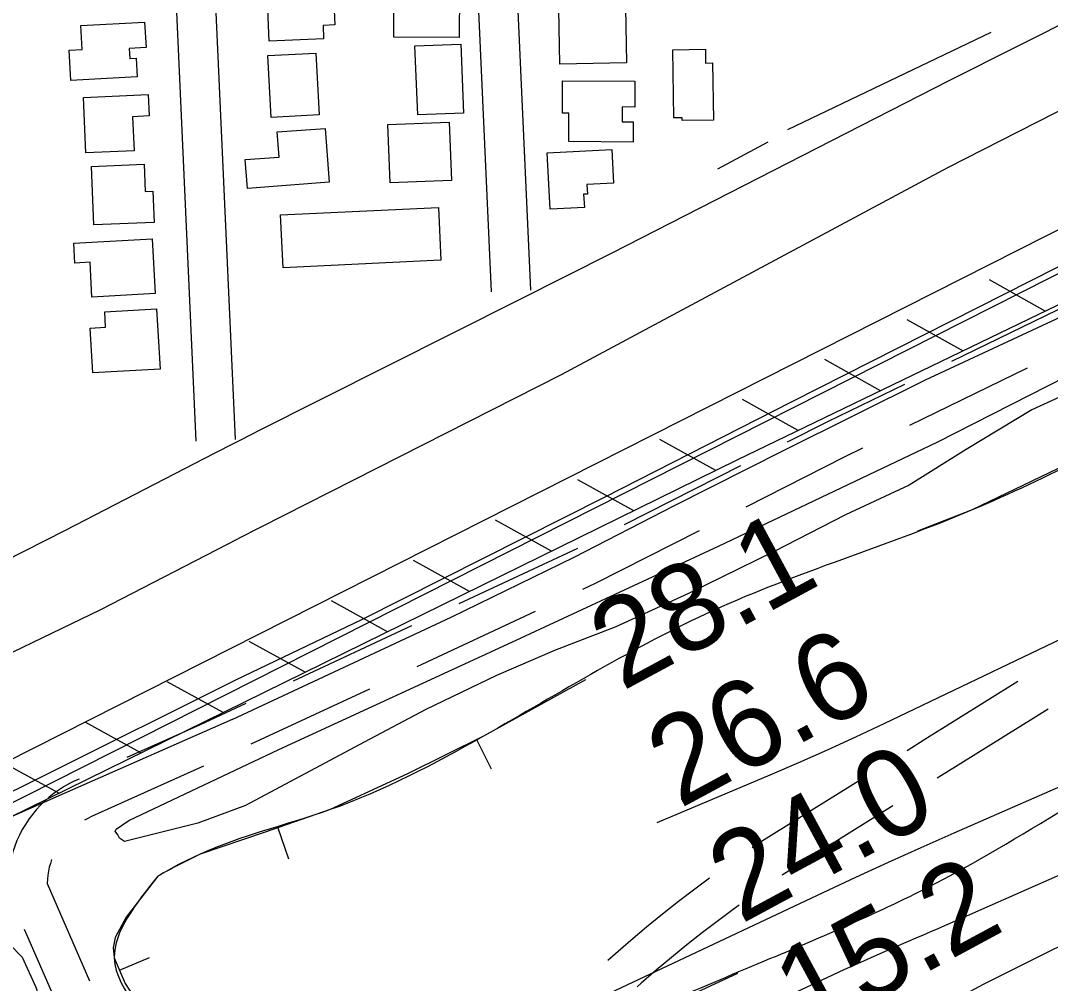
# Model space of a CAD drawing. Extents: x 3598634 to 3636690, y 517270 to 542944.
# Drawn here: x 3610665 to 3611452, y 535580 to 536317 of the extents above; entities that cross this region are included whole.
import ezdxf

# ---------------------------------------------------------------- set-up
doc = ezdxf.new("R2010")
doc.units = 0
for name, color, linetype in [('V-BLDG-OTLN', 7, 'Continuous'), ('V-BORW-LINE', 7, 'Continuous'), ('V-FLOD-BASE', 7, 'Continuous'), ('V-LEVE-TOET', 7, 'Continuous'), ('V-RIVR-RANG', 7, 'Continuous'), ('V-ROAD-CNTR', 7, 'Continuous'), ('V-RRAP-FSHR', 7, 'Continuous'), ('V-SITE-VEGE', 7, 'Continuous'), ('V-SURV-LINE', 7, 'Continuous'), ('V-TOPO-DPTH', 7, 'Continuous'), ('V-TOPO-MAJR', 7, 'Continuous'), ('V-TOPO-MINR', 7, 'Continuous'), ('V-TOPO-SHOR', 7, 'Continuous')]:
    doc.layers.add(name, color=color, linetype=linetype)

msp = doc.modelspace()

# ---------------------------------------------------------------- linework, layer by layer
at = {"layer": 'V-BLDG-OTLN'}
for points in [[(3610852.94, 536344.03), (3610893.77, 536345.78), (3610894.19, 536336.04), (3610904.04, 536336.46), (3610905.02, 536313.64), (3610895.97, 536313.26), (3610896.41, 536302.93), (3610854.78, 536301.15)], [(3611000.22, 536304.1), (3610950.08, 536304.35), (3610950.21, 536329.05), (3610961.4, 536329), (3610961.51, 536350.75), (3610986.63, 536350.62), (3610986.57, 536339.04), (3611000.4, 536338.97)], [(3611128.09, 536284.69), (3611077.2, 536283.66), (3611076.34, 536325.66), (3611127.24, 536326.69)], [(3610710.66, 536313.19), (3610759.46, 536315.83), (3610760.52, 536296.26), (3610747.64, 536295.56), (3610748.05, 536287.98), (3610753.05, 536288.25), (3610753.83, 536273.92), (3610702.89, 536271.15), (3610701.63, 536294.28), (3610711.66, 536294.82)], [(3610968.38, 536244.8), (3610966.31, 536297.49), (3611001.26, 536298.87), (3611003.33, 536246.17)], [(3610893, 536244.84), (3610856.28, 536242.85), (3610853.73, 536290.12), (3610890.45, 536292.1)], [(3611164.33, 536242.43), (3611163.56, 536294.59), (3611188.47, 536294.96), (3611188.63, 536284.42), (3611193.93, 536284.5), (3611194.58, 536240.84), (3611170.81, 536240.48), (3611170.79, 536242.52)], [(3611083.92, 536224.31), (3611084.07, 536246.16), (3611079.11, 536246.19), (3611079.28, 536270.89), (3611134.63, 536270.52), (3611134.5, 536250.76), (3611124.93, 536250.82), (3611124.85, 536239.45), (3611133.22, 536239.39), (3611133.12, 536223.98)], [(3610714.57, 536215.6), (3610712.6, 536258.12), (3610762.1, 536260.41), (3610762.86, 536243.94), (3610750.12, 536243.35), (3610751.33, 536217.3)], [(3610945.53, 536237.48), (3610992.58, 536239.27), (3610994.27, 536194.55), (3610947.23, 536192.77)], [(3610860.98, 536231.66), (3610897.48, 536234.41), (3610900.58, 536193.26), (3610838.09, 536188.54), (3610836.43, 536210.49), (3610862.43, 536212.45)], [(3611067.51, 536215.74), (3611116.86, 536218.3), (3611118.2, 536192.49), (3611097.85, 536191.44), (3611098.23, 536184.12), (3611095.34, 536183.97), (3611095.87, 536173.84), (3611069.76, 536172.48)], [(3610766.69, 536162.47), (3610720.68, 536160.52), (3610718.78, 536205.2), (3610759.09, 536206.91), (3610759.97, 536186.24), (3610765.67, 536186.48)], [(3610863.5, 536168.16), (3610984.26, 536173.91), (3610986.19, 536133.44), (3610865.43, 536127.68)], [(3610705.31, 536146.62), (3610765.26, 536149.94), (3610767.57, 536108.05), (3610719.14, 536105.37), (3610717.67, 536131.98), (3610706.15, 536131.34)], [(3610768.59, 536096.26), (3610771.25, 536050.25), (3610719.73, 536047.27), (3610717.74, 536081.6), (3610729.62, 536082.29), (3610728.94, 536093.96)]]:
    msp.add_lwpolyline(points, close=True, dxfattribs=at)
at = {"layer": 'V-BORW-LINE'}
for p, q in [((3611013.49, 535766.62), (3611024.62, 535744.24)), ((3610861.42, 535699.1), (3610869.62, 535675.48)), ((3610740.25, 535590.16), (3610763.25, 535599.96))]:
    msp.add_line(p, q, dxfattribs=at)
for points in [[(3612023.85, 536263.17), (3611980.78, 536247.05), (3611892.58, 536209.71), (3611807.94, 536161.5), (3611723.45, 536113.04), (3611642.68, 536069.34), (3611561.62, 536026.13), (3611477.6, 535983.35), (3611392.7, 535942.4), (3611350.75, 535926.22)], [(3611096.73, 535812.4), (3611018.78, 535769.25), (3610960.51, 535740.3), (3610901.46, 535713), (3610851.78, 535695.75), (3610801.89, 535678.85), (3610785.43, 535671.05), (3610769.5, 535662.11)], [(3610769.5, 535662.11), (3610745.31, 535630.77), (3610736.96, 535615.08), (3610735.41, 535607.29), (3610736.24, 535599.58), (3610744.62, 535579.91), (3610782.45, 535521.14), (3610796.61, 535489.26), (3610804.12, 535473.17), (3610813.88, 535457.77), (3610825.62, 535446.59), (3610838.02, 535440.11), (3610863.05, 535435.2), (3610883.35, 535435.96), (3610913.73, 535442.49), (3610940.89, 535453.25), (3611010.93, 535490.43), (3611081.63, 535526.87), (3611157.62, 535562.1), (3611213.26, 535587.79)]]:
    msp.add_lwpolyline(points, dxfattribs=at)
msp.add_spline([(3610769.5, 535662.11), (3610801.89, 535678.85), (3610901.46, 535713), (3611018.78, 535769.25), (3611194.65, 535865.45), (3611392.7, 535942.4), (3611561.62, 536026.13), (3611723.45, 536113.04), (3611892.58, 536209.71), (3612070.48, 536280.62), (3612177.1, 536337.19), (3612328.43, 536346.09), (3612365.39, 536274.98), (3612320.44, 536188.1), (3612159.82, 536071.64), (3611939.35, 535952.99), (3611770.69, 535869.03), (3611577.59, 535780.59), (3611364.8, 535656.78), (3611233.69, 535597.22), (3611081.63, 535526.87), (3610940.89, 535453.25), (3610813.88, 535457.77), (3610782.45, 535521.14), (3610736.24, 535599.58), (3610769.5, 535662.11)], degree=3, dxfattribs=at)
at = {"layer": 'V-FLOD-BASE'}
for points in [[(3613126.88, 536947.9), (3613005.88, 536895.75), (3612842.67, 536822.62), (3612628.59, 536720.77), (3612427.84, 536620.78), (3612265.19, 536538.42), (3612118.66, 536463.83), (3611925.34, 536363.88), (3611722.56, 536259.52), (3611477.81, 536138.03), (3611254.56, 536025.11), (3611111.09, 535951.82), (3610925.94, 535858.58), (3610829.1, 535812.18)], [(3610829.1, 535812.18), (3610682.85, 535739.24), (3610548.17, 535672.38), (3610508.72, 535652.79), (3610480.82, 535635.89), (3610442.72, 535611.55), (3610412.09, 535588.54), (3610378.04, 535560.11), (3610264.32, 535459.22)]]:
    msp.add_lwpolyline(points, dxfattribs=at)
at = {"layer": 'V-LEVE-TOET'}
for points in [[(3613678.75, 537323.7), (3613393.93, 537188.74), (3613238.46, 537113.49), (3613220.45, 537105.54), (3613196.7, 537095.05), (3613084.29, 537034.65), (3612874.5, 536938.84), (3612572.47, 536804.82), (3612341.69, 536695.81), (3612081.23, 536565.59), (3611875.04, 536468.26), (3611591.08, 536315.07), (3611373.66, 536204.33), (3611078.17, 536045.69), (3610830.76, 535920.18)], [(3610826.51, 535782.03), (3610993.88, 535860.21), (3611087.99, 535906.32), (3611164.46, 535945.43), (3611248.85, 535988.16), (3611356.77, 536042.04), (3611457.04, 536088.7), (3611536.58, 536127.31), (3611632.74, 536173.43), (3611724.28, 536222.36), (3611836.02, 536282.41), (3611934.24, 536329.06), (3612029.61, 536379.54), (3612118.59, 536427.43), (3612198.89, 536468.09), (3612286.11, 536509.3), (3612375.87, 536555.39), (3612453.87, 536594.25), (3612521.87, 536632.79), (3612612.67, 536675.56)], [(3610613.78, 535812.11), (3610726, 535866.13), (3610830.76, 535920.18)], [(3610826.51, 535782.03), (3610633.37, 535696.99)]]:
    msp.add_lwpolyline(points, dxfattribs=at)
at = {"layer": 'V-ROAD-CNTR'}
for p, q in [((3611466.65, 536099.75), (3611376.73, 536055.99)), ((3611434.68, 536050.83), (3611344.76, 536007.07)), ((3611215.42, 535976.13), (3611126.23, 535930.91)), ((3611090.55, 535912.84), (3610999.96, 535870.5)), ((3611058.24, 535864.62), (3610967.65, 535822.29)), ((3610963.72, 535853.57), (3610873.13, 535811.23)), ((3610931.41, 535805.35), (3610840.81, 535763.01)), ((3610667.38, 535621.59), (3610707.42, 535529.96))]:
    msp.add_line(p, q, dxfattribs=at)
for points in [[(3613504.37, 537298.19), (3613263.07, 537189.72), (3613226.18, 537173.13), (3612903.99, 537025.29), (3612651.67, 536909.6), (3612381.21, 536778.17), (3612102.85, 536636.7), (3612024.44, 536597.32), (3611881.03, 536525.28), (3611648.71, 536408.92), (3611528.47, 536348.32), (3611374.7, 536270.81), (3611116.81, 536138.94), (3611045.59, 536103.07), (3610844.51, 536001.96)], [(3610979.38, 537109.97), (3611024.59, 536109.29)], [(3611009.35, 537111.33), (3611054.56, 536110.65)], [(3610749.63, 537082.42), (3610798.67, 535995.03)], [(3610779.6, 537083.77), (3610828.64, 535996.38)], [(3611340.77, 536038.49), (3611281.9, 536009.84), (3611251.1, 535994.22)], [(3610605.3, 535879.54), (3610698.94, 535926.98), (3610813.03, 535985.75), (3610844.51, 536001.96)], [(3611308.79, 535989.56), (3611295.25, 535982.97), (3611219.49, 535944.56)], [(3611183.82, 535926.47), (3611104.24, 535886.12), (3611094.48, 535881.56)], [(3611427.62, 535811.05), (3611356.47, 535766.71), (3611342.76, 535758.15)], [(3610836.89, 535794.29), (3610802.06, 535778.02), (3610745.9, 535752.81)], [(3611450.63, 535790.04), (3611372.35, 535741.26), (3611365.77, 535737.15)], [(3610804.51, 535746.23), (3610718.8, 535707.77), (3610715.91, 535706.36), (3610713.43, 535704.98)], [(3610709.41, 535736.44), (3610706.07, 535734.94), (3610702.03, 535732.97), (3610697.96, 535730.7), (3610694.01, 535728.23), (3610690.2, 535725.54), (3610686.54, 535722.67), (3610683.04, 535719.6), (3610679.71, 535716.35), (3610676.55, 535712.93), (3610673.58, 535709.34), (3610670.8, 535705.61), (3610668.23, 535701.73), (3610665.86, 535697.72), (3610663.71, 535693.59), (3610661.78, 535689.35), (3610660.08, 535685.01), (3610658.61, 535680.6), (3610657.38, 535676.11), (3610656.39, 535671.56), (3610656.26, 535670.77)], [(3611308.84, 535736.95), (3611231.51, 535688.62), (3611224.23, 535683.67)], [(3611331.85, 535715.95), (3611247.9, 535663.49), (3611247.07, 535662.92)], [(3610688.32, 535674.86), (3610688.3, 535674.8), (3610687.33, 535671.89), (3610686.52, 535668.93), (3610685.87, 535665.94), (3610685.37, 535662.91), (3610685.04, 535659.87), (3610684.87, 535656.81), (3610684.87, 535656.5), (3610717.39, 535582.08)], [(3611191.58, 535660.57), (3611180.33, 535652.19), (3611167.91, 535642.65), (3611155.62, 535632.94), (3611143.48, 535623.05), (3611131.48, 535612.98), (3611119.62, 535602.74), (3611113.9, 535597.65)], [(3611214.29, 535640), (3611210.64, 535637.36), (3611198.43, 535628.26), (3611186.35, 535618.99), (3611174.4, 535609.54), (3611162.59, 535599.92), (3611150.92, 535590.14), (3611139.4, 535580.18), (3611136.32, 535577.45)]]:
    msp.add_lwpolyline(points, dxfattribs=at)
at = {"layer": 'V-RRAP-FSHR'}
for p, q in [((3611448.49, 536094.6), (3611405.87, 536118.43)), ((3611385.47, 536064.14), (3611342.84, 536087.97)), ((3611322.44, 536033.68), (3611279.82, 536057.51)), ((3611259.41, 536003.22), (3611216.79, 536027.05)), ((3611196.44, 535972.66), (3611153.66, 535996.2)), ((3611133.62, 535941.78), (3611090.84, 535965.33)), ((3611070.79, 535910.91), (3611028.01, 535934.45)), ((3611007.97, 535880.03), (3610965.19, 535903.58)), ((3610945.15, 535849.16), (3610902.37, 535872.71)), ((3610882.32, 535818.28), (3610839.55, 535841.83)), ((3610819.5, 535787.41), (3610776.72, 535810.96)), ((3610756.68, 535756.54), (3610713.9, 535780.08)), ((3610693.85, 535725.66), (3610651.08, 535749.21))]:
    msp.add_line(p, q, dxfattribs=at)
for points in [[(3610283.69, 535468.85), (3610304.82, 535469.21), (3610403.34, 535553.55), (3610452.08, 535596.07), (3610565.02, 535662.34), (3611212.78, 535980.69), (3611755.64, 536243.03), (3612146.76, 536451.69), (3612655.72, 536703.7), (3613040.11, 536882.25), (3613115.54, 536910.69), (3613121.06, 536940.01)], [(3610283.69, 535468.85), (3610304.82, 535469.21), (3610403.34, 535553.55), (3610452.08, 535596.07), (3610565.02, 535662.34), (3611212.78, 535980.69), (3611755.64, 536243.03), (3611986.38, 536366.13)]]:
    msp.add_lwpolyline(points, dxfattribs=at)
at = {"layer": 'V-SITE-VEGE'}
for points in [[(3611498.35, 536046.44), (3611438.15, 536018.92), (3611387.98, 535988.62), (3611344.47, 535961.44), (3611295.8, 535938.6), (3611240.48, 535910.32), (3611175.68, 535878.41), (3611119.84, 535852.97), (3611072.94, 535834.75), (3611028.62, 535815.79), (3610974.57, 535789.57), (3610927.46, 535764.69), (3610901.08, 535750.69), (3610836.55, 535716.21), (3610800.16, 535702.67), (3610744, 535688.52), (3610740.14, 535691.07), (3610738.84, 535693.63), (3610737.03, 535696.44), (3610737.79, 535697.99), (3610747.25, 535704.71), (3610862.01, 535758.96), (3611040.3, 535841.27), (3611198.61, 535914.73), (3611365.87, 535994.16), (3611521.58, 536073.52)], [(3610656.09, 535609.95), (3610665.81, 535600.17), (3610676.2, 535577.16), (3610695.52, 535515.81), (3610704.49, 535484.44), (3610709.3, 535462.14), (3610716.83, 535418.24), (3610719.53, 535386.2), (3610721.57, 535368.78), (3610725.71, 535355.54), (3610729.17, 535347.17), (3610728.45, 535337.42), (3610725.64, 535329.07), (3610720.03, 535317.94), (3610713.05, 535311), (3610703.28, 535305.46), (3610699.8, 535306.86), (3610700.51, 535309.64), (3610699.25, 535359.1), (3610691.7, 535394.64), (3610684.12, 535424.6), (3610679.3, 535444.82), (3610671.72, 535474.09), (3610661.38, 535509.64)]]:
    msp.add_lwpolyline(points, dxfattribs=at)
at = {"layer": 'V-SURV-LINE'}
for points in [[(3610459.45, 535651.34), (3612525.02, 536696.93)], [(3612538.59, 536670.17), (3610473.02, 535624.59)]]:
    msp.add_lwpolyline(points, dxfattribs=at)
at = {"layer": 'V-TOPO-DPTH'}
msp.add_lwpolyline([(3612876.2, 536336.53), (3612348.28, 536059.45), (3612325.59, 536047.59), (3612302.86, 536035.78), (3612280.1, 536024.04), (3612257.32, 536012.36), (3611942.51, 535851.61), (3611849.6, 535804.33), (3611756.6, 535757.23), (3611663.47, 535710.38), (3611570.25, 535663.7), (3611418.28, 535587.87), (3611401.07, 535579.07), (3611383.98, 535570.06), (3611367.07, 535560.71), (3611350.27, 535551.15), (3610876.51, 535174.19), (3610843.92, 535147.98), (3610810.12, 535123.16), (3610480.34, 534897.5)], dxfattribs=at)
at = {"layer": 'V-TOPO-MAJR'}
msp.add_lwpolyline([(3611496.64, 535860.84), (3611325.1, 535778.8), (3611303.4, 535768.61), (3611281.62, 535758.62), (3611259.69, 535748.93), (3611237.68, 535739.44), (3611151.44, 535702.98)], dxfattribs=at)
at = {"layer": 'V-TOPO-MINR'}
for points in [[(3612876.2, 536336.53), (3612348.28, 536059.45), (3612325.59, 536047.59), (3612302.86, 536035.78), (3612280.1, 536024.04), (3612257.32, 536012.36), (3611942.51, 535851.61), (3611849.6, 535804.33), (3611756.6, 535757.23), (3611663.47, 535710.38), (3611570.25, 535663.7), (3611418.28, 535587.87), (3611401.07, 535579.07), (3611383.98, 535570.06), (3611367.07, 535560.71), (3611350.27, 535551.15), (3610876.51, 535174.19), (3610843.92, 535147.98), (3610810.12, 535123.16), (3610480.34, 534897.5)], [(3611795.85, 535811.37), (3611364.41, 535621.09), (3611361.12, 535619.64), (3611357.83, 535618.2), (3611354.54, 535616.77), (3611351.24, 535615.35), (3611332.4, 535607.23), (3611319.7, 535601.69), (3611307.05, 535596.07), (3611294.44, 535590.33), (3611281.87, 535584.52), (3611180.63, 535537.12), (3611117.48, 535507.55), (3611054.32, 535477.96), (3610991.17, 535448.36), (3610928.03, 535418.75), (3610448.72, 535193.92)], [(3611572.59, 535780.06), (3611378.58, 535695.04), (3611353.39, 535683.87), (3611328.27, 535672.57), (3611303.25, 535661.05), (3611278.29, 535649.39), (3611115.42, 535572.47), (3611009.44, 535521.53), (3610903.94, 535469.63), (3610799.16, 535416.28), (3610694.86, 535361.97), (3610279.15, 535141.89)]]:
    msp.add_lwpolyline(points, dxfattribs=at)
at = {"layer": 'V-TOPO-SHOR'}
for p, q in [((3611406.95, 536307.76), (3611251.22, 536233.2)), ((3611236.15, 536223.87), (3611197.63, 536203.33))]:
    msp.add_line(p, q, dxfattribs=at)

# ---------------------------------------------------------------- texts
at = {"layer": 'V-RIVR-RANG'}
for s, p in [('28.1', (3611124.79, 535803.38)), ('26.6', (3611168.8, 535713.5)), ('24.0', (3611215.6, 535625.12)), ('15.2', (3611265.88, 535538.63))]:
    msp.add_text(s, height=67, rotation=28.36833, dxfattribs=at).set_placement(p)

doc.saveas('drawing.dxf')
